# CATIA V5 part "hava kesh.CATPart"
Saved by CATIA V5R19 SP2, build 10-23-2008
Part number: hava kesh
Bounding box of the stored display mesh (mm): x -1327.075 to 1932.57, y -725.14 to 725.14, z 15.998 to 1015.618
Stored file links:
  C:\BEHROOZ\catia learning\tarh haye mashin\hb\hava kesh.CATPart
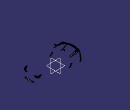
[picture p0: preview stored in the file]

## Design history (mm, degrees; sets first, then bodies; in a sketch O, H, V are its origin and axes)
Body1 (main body)
  Set1
    DatumSurface1
    ThickSurface1: Surface DatumSurface1, TopOffset 0.1, BotOffset 0.1
    DatumSurface2
    ThickSurface2: Surface DatumSurface2, TopOffset 0.1, BotOffset 0.1
    DatumSurface3
    DatumSurface4
    ThickSurface3: Surface DatumSurface4, TopOffset 0.1, BotOffset 0.1
    DatumSurface5
    ThickSurface4: Surface DatumSurface5, TopOffset 0.1, BotOffset 0.1
    DatumSurface6
    ThickSurface5: Surface DatumSurface6, TopOffset 0.1, BotOffset 0.1
    DatumSurface7
    ThickSurface6: Surface DatumSurface7, TopOffset 0.1, BotOffset 0.1
    DatumSurface8
    ThickSurface7: Surface DatumSurface8, TopOffset 0.1, BotOffset 0.1
    DatumSurface9
    ThickSurface8: Surface DatumSurface9, TopOffset 0.1, BotOffset 0.1
    DatumSurface10
    ThickSurface9: Surface DatumSurface10, TopOffset 0.1, BotOffset 0.1
    DatumSurface11
    ThickSurface10: Surface DatumSurface11, TopOffset 0.1, BotOffset 0.1
    DatumSurface12
    DatumSurface13
    ThickSurface11: Surface DatumSurface12, TopOffset 0.1, BotOffset 0.1
    DatumSurface14 to DatumSurface27
    ThickSurface12: Surface DatumSurface22, TopOffset 0.1, BotOffset 0.1
    Plane1: stored without definition
    ThickSurface13: Surface DatumSurface26, TopOffset 0.1, BotOffset 0.1
    DatumCurve1 to DatumCurve16
  Plane2: stored without definition
  ThickSurface14: Surface DatumSurface3, TopOffset 0.1, BotOffset 0.1
  DatumCurve17 to DatumCurve24
  Sketch1 on Plane2, origin (-1447, 0, 0), H (0, 1, 0), V (0, 0, 1)
    projected arc E1 centre (304.5491, 556.1301) radius 27.7678 from (278.6077, 546.2259) to (297.5311, 529.2638) ccw from edge of DatumCurve17
    projected line E2 (278.6077, 546.2259) -> (273.5934, 559.3558) from edge of DatumCurve18
    projected arc E3 centre (278.6775, 561.2976) radius 5.4423 from (279.5258, 566.6734) to (273.5934, 559.3558) ccw from edge of DatumCurve19
    projected curve E4 from edge of DatumCurve20
    projected arc E5 centre (335.2878, 525.7613) radius 26.0411 from (359.6201, 535.0392) to (344.7785, 550.0113) ccw from edge of DatumCurve21
    projected line E6 (359.6201, 535.0392) -> (366.5256, 516.9572) from edge of DatumCurve22
    projected arc E7 centre (360.3645, 514.6028) radius 6.5956 from (357.644, 508.5944) to (366.5256, 516.9572) ccw from edge of DatumCurve23
    projected curve E8 from edge of DatumCurve24
    point P17 (-297.5311, 529.2638)
    point P18 (-278.6077, 546.2259)
    point P19 (-273.5934, 559.3558)
    point P20 (-278.6077, 546.2259)
    point P21 (-273.5934, 559.3558)
    point P22 (-279.5258, 566.6734)
    point P23 (-344.7785, 550.0113)
    point P24 (-279.5258, 566.6734)
    point P25 (-344.7785, 550.0113)
    point P26 (-359.6201, 535.0392)
    point P27 (-366.5256, 516.9572)
    point P28 (-359.6201, 535.0392)
    point P29 (-366.5256, 516.9572)
    point P30 (-357.644, 508.5944)
    point P31 (-297.5311, 529.2638)
    point P32 (-357.644, 508.5944)
    arc A1 centre (-304.5491, 556.1301) radius 27.7678 from (-278.6077, 546.2259) to (-297.5311, 529.2638) cw
    line L1 (-278.6077, 546.2259) -> (-273.5934, 559.3558)
    arc A2 centre (-278.6775, 561.2976) radius 5.4423 from (-279.5258, 566.6734) to (-273.5934, 559.3558) cw
    frozenspline C1
    arc A3 centre (-335.2878, 525.7613) radius 26.0411 from (-359.6201, 535.0392) to (-344.7785, 550.0113) cw
    line L2 (-359.6201, 535.0392) -> (-366.5256, 516.9572)
    arc A4 centre (-360.3645, 514.6028) radius 6.5956 from (-357.644, 508.5944) to (-366.5256, 516.9572) cw
    frozenspline C2
    coincidence: P17 P31, P18 P20, P19 P21, P22 P24, P23 P25, P26 P28, P27 P29, P30 P32
  Pocket1: profile Sketch1, direction (-1, 0, 0), length 20, opposite side length 187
